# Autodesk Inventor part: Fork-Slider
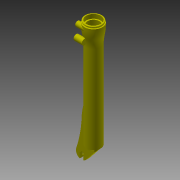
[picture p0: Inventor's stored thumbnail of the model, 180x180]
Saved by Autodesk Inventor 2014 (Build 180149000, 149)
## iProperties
Shininess: 11.0
Length Units: 11272
Angle Units: 11279
Time Units: 11290
Mass Units: 11286
Length Display Precision: 3
Angle Display Precision: 2
Compacted: True
Created: 2001-11
Part Number: Fork-Slider
Document SubType Name: Modeling
Designer: Autodesk, Inc.
Mass: 115.043 g
Surface Area: 625.932 cm^2
Volume: 115.043 cm^3
Density: 1 g/cm^3
Material: Generic
Appearance: Yellow (Flat)
Density: 0.0
Volumn: 0.0
Area: 0.0
PropertySet Name: Model Information
Control State: 0
Master: False
Checked Out: False
Author: Autodesk, Inc.
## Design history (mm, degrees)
node "WorkPlane1"
node "WorkPlane2"
workplane "Work Plane3"
node "WorkPlane3"
sketch "Sketch1"
  geometry: L1 (-491.904, 893.583)-(-489.986, 893.583); L2 (-491.94, 890.889)-(-492.507, 891.195); L3 (-493.987, 888.502)-(-492.544, 888.502); L4 (-493.987, 883.604)-(-493.987, 888.502); L5 (-491.593, 861.235)-(-492.38, 865.605); L6 (-489.986, 628.153)-(-489.986, 843.237); L7 (-477.096, 614.183)-(-489.986, 628.153); L8 (-475.254, 614.183)-(-477.096, 614.183); L9 (-475.254, 630.693)-(-475.254, 614.183); L10 (-486.875, 630.693)-(-475.254, 630.693); L11 (-486.875, 883.423)-(-486.875, 630.693); L12 (-489.986, 883.423)-(-486.875, 883.423); L13 (-489.986, 893.583)-(-489.986, 883.423); L14 (-472.221, 864.964)-(-472.221, 656.569); L15 (-472.221, 864.964)-(-472.221, 656.569); A1 r 1.27 centre (-491.904, 892.313) between (-491.904, 893.583) and (-492.507, 891.195); A2 r 1.27 centre (-492.544, 889.772) between (-492.544, 888.502) and (-491.94, 890.889); A3 r 101.6 centre (-392.387, 883.604) between (-493.987, 883.604) and (-492.38, 865.605); A4 r 101.6 centre (-591.586, 843.237) between (-489.986, 843.237) and (-491.593, 861.235)
  constraints: 30 end point, 8 point on circle, 7 tangent, 6 vertical, 5 horizontal, 4 centre point, 1 collinear, 1 other
revolve "RevolutionFull1" sketch "Sketch1" stored, may be unused: angle "d2" = 360 deg
sketch "Sketch2"
  geometry: L1 (-468.069, 628.153)-(-489.986, 628.153); L2 (-468.069, 735.894)-(-468.069, 628.153); L3 (-450.045, 605.991)-(-450.045, 592.726); L4 (-458.808, 592.726)-(-458.808, 605.991); L5 (-467.317, 599.747)-(-465.345, 597.277); L6 (-489.986, 628.153)-(-467.317, 599.747); A1 r 136.444 centre (-590.87, 676.421) between (-454.426, 676.794) and (-468.069, 735.894); A2 r 273.047 centre (-182.07, 696.209) between (-454.426, 676.794) and (-440.731, 608.748); A3 r 13.97 centre (-454.426, 605.991) between (-450.045, 592.726) and (-440.731, 608.748); A4 r 4.382 centre (-454.426, 605.991) between (-450.045, 605.991) and (-458.808, 605.991); A5 r 13.97 centre (-454.426, 605.991) between (-465.345, 597.277) and (-458.808, 592.726)
  constraints: 12 end point, 10 point on circle, 5 centre point
extrude "ExtrusionBlind1" join sketch "Sketch2" distance "d3" = 9.652; taper "d4" = 0 deg
node "WorkAxis1"
workplane "Work Plane5"
workplane "Work Plane6"
node "WorkPlane4"
workplane "Work Plane8"
node "WorkPlane5"
sketch "Sketch3"
  geometry: L1 (0, -4.165)-(0, 0); L2 (9.652, -4.076)-(9.652, -4.165); L3 (0, -4.165)-(9.652, -4.165); A1 r 17.766 centre (11.43, 13.6) between (0, 0) and (9.652, -4.076)
  constraints: 6 end point, 2 point on circle, 1 centre point
extrude "ExtrusionThru1" cut sketch "Sketch3" stored distance "d17" = 3.302; taper "d18" = 0 deg
sketch "Sketch4"
  geometry: C1 r 14.654 at (14.546, 1.778)
  constraints: 1 centre point
extrude "ExtrusionThru2" cut sketch "Sketch4" stored distance "d19" = 3.302; taper "d20" = 0 deg
sketch "Sketch5"
  geometry: L1 (-458.808, 605.991)-(-458.808, 592.726) reference; L2 (-450.045, 592.726)-(-450.045, 605.991) reference; A1 r 4.382 centre (-454.426, 605.991) between (-450.045, 605.991) and (-458.808, 605.991) reference; A2 r 10.668 centre (-454.426, 605.991) between (-450.045, 596.265) and (-458.808, 596.265)
  constraints: 2 point on circle, 2 point on line, 1 centre point
extrude "ExtrusionBlind2" cut sketch "Sketch5" distance "d21" = 4.572; taper "d22" = 0 deg
sketch "Sketch6"
  geometry: C1 r 6.985 at (-100.202, 21.766)
  constraints: 1 centre point
extrude "ExtrusionBlind3" join sketch "Sketch6" distance "d23" = 20.32; taper "d24" = 0 deg
node "Sketch7"
sketch "Sketch8"
  geometry: L1 (-126.546, 21.766)-(-131.444, 21.766) reference; L2 (-106.924, 19.867)-(-104.178, 19.373) reference; L3 (-108.547, 20.159)-(-106.924, 19.867) reference; L4 (-131.444, 21.766)-(-126.546, 21.766) reference; L5 (-131.444, 20.323)-(-131.444, 21.766) reference; L6 (-134.137, 20.286)-(-133.831, 19.719) reference; L7 (-136.525, 17.766)-(-136.525, 19.683) reference; L8 (-126.365, 17.766)-(-136.525, 17.766) reference; L9 (-126.365, 14.654)-(-126.365, 17.766) reference; L10 (126.365, 14.654)-(-126.365, 14.654) reference; L11 (126.365, 1.587)-(126.365, 14.654) reference; L12 (135.255, 1.587)-(126.365, 1.587) reference; L13 (135.255, 3.034)-(135.255, 1.587) reference; L14 (151.166, 3.034)-(135.255, 3.034) reference; L15 (151.166, 11.43)-(151.166, 3.034) reference; L16 (135.771, 11.43)-(151.166, 11.43) reference; L17 (128.905, 17.766)-(135.771, 11.43) reference; L18 (-86.179, 17.766)-(128.905, 17.766) reference; L19 (-104.178, -19.373)-(-108.547, -20.159) reference; L20 (-126.546, -21.766)-(-131.444, -21.766) reference; L21 (-131.444, -21.766)-(-131.444, -20.323) reference; L22 (-133.831, -19.719)-(-134.137, -20.286) reference; L23 (-136.525, -19.683)-(-136.525, -17.766) reference; L24 (-136.525, -17.766)-(-126.365, -17.766) reference; L25 (-126.365, -17.766)-(-126.365, -14.654) reference; L26 (-126.365, -14.654)-(126.365, -14.654) reference; L27 (126.365, -14.654)-(126.365, -1.587) reference; L28 (126.365, -1.587)-(135.255, -1.587) reference; L29 (135.255, -1.587)-(135.255, -3.034) reference; L30 (135.255, -3.034)-(142.875, -3.034) reference; L31 (142.875, -3.034)-(142.875, -4.875) reference; L32 (142.875, -4.875)-(128.905, -17.766) reference; L33 (128.905, -17.766)-(-86.179, -17.766) reference; C1 r 6.35 at (-124.333, 15.39); A1 r 6.985 centre (-100.202, 21.766) between (-94.264, 18.088) and (-106.924, 19.867) reference; A2 r 101.6 centre (-86.179, 119.366) between (-104.178, 19.373) and (-94.264, 18.088) reference; A3 r 101.6 centre (-126.546, -79.834) between (-108.547, 20.159) and (-123.263, 21.713) reference; A4 r 101.6 centre (-126.546, -79.834) between (-125.109, 21.756) and (-126.546, 21.766) reference; A5 r 1.27 centre (-132.714, 20.323) between (-133.831, 19.719) and (-131.444, 20.323) reference; A6 r 1.27 centre (-135.255, 19.683) between (-134.137, 20.286) and (-136.525, 19.683) reference; A7 r 101.6 centre (-86.179, 119.366) between (-94.264, 18.088) and (-86.179, 17.766) reference; A8 r 101.6 centre (-126.546, -79.834) between (-123.263, 21.713) and (-125.109, 21.756) reference; A9 r 101.6 centre (-86.179, -119.366) between (-86.179, -17.766) and (-104.178, -19.373) reference; A10 r 101.6 centre (-126.546, 79.834) between (-126.546, -21.766) and (-108.547, -20.159) reference; A11 r 1.27 centre (-132.714, -20.323) between (-131.444, -20.323) and (-133.831, -19.719) reference; A12 r 1.27 centre (-135.255, -19.683) between (-136.525, -19.683) and (-134.137, -20.286) reference
  constraints: 1 centre point, 1 tangent
extrude "ExtrusionBlind4" join sketch "Sketch8" distance "d26" = 23.368; taper "d27" = 0 deg
node "Sketch9"
extrude "ExtrusionToPlane1" cut stored distance "d29" = 3.302; taper "d30" = 0 deg
  node "Sketch10"
extrude "ExtrusionBlind5" cut distance "d31" = 50.8; taper "d32" = 0 deg
  node "Sketch11"
workplane "Work Plane10"
sketch "Sketch13"
  geometry: C1 r 3.034 at (0, 0); A1 r 3.034 centre (0, 0) between (-2.458, 1.778) and (2.458, 1.778) reference
  constraints: 1 centre point, 1 coincident, 1 concentric
workplane "Work Plane11"
extrude "Extrusion9" join sketch "Sketch13" stored distance "d34" = 25.4; taper "d35" = 0 deg
sketch "Sketch14"
  geometry: L1 (-2.458, 1.778)-(2.458, 1.778) reference; C1 r 3.034 at (0, 0); A1 r 3.034 centre (0, 0) between (-2.458, 1.778) and (2.458, 1.778) reference
  constraints: 1 centre point, 1 coincident, 1 concentric
extrude "Extrusion10" cut sketch "Sketch14" stored distance "d36" = 25.4; taper "d37" = 0 deg
sketch "Sketch15"
  geometry: C1 r 3.034 at (0, 0) reference
hole "Hole1" sketch "Sketch15" at (0, 0) diameter "d38" = 3.175; stored, may be unused: countersink angle "d42" = 82 deg, drill point angle "d44" = 118 deg; dims "d39" = 12.7, "d40" = 9.525, "d41" = 6.35, "d43" = 19.05
sketch "Sketch16"
  geometry: C1 r 6.985 at (0, 0) reference
hole "Hole2" sketch "Sketch16" at (0, 0) diameter "d45" = 4.3434; stored, may be unused: countersink angle "d49" = 82 deg, drill point angle "d51" = 118 deg; dims "d46" = 12.7, "d47" = 9.525, "d48" = 6.35, "d50" = 12.7
sketch "Sketch17"
  geometry: C1 r 6.35 at (0, 0) reference
hole "Hole3" sketch "Sketch17" at (0, 0) diameter "d52" = 3.2512; stored, may be unused: countersink angle "d56" = 82 deg, drill point angle "d58" = 118 deg; dims "d53" = 12.7, "d54" = 9.525, "d55" = 6.35, "d57" = 12.7
body "Solid1"
other parameters: "d0" = -11.43, "d1" = -19.05, "d5" = 0, "d6" = 0, "d7" = 0, "d8" = 0, "d9" = 0, "d10" = 0, "d11" = 0, "d12" = 0, "d13" = 0, "d14" = 0, "d15" = 0, "d16" = 0, "d25" = 0, "d28" = 0, "d33" = -7.62
